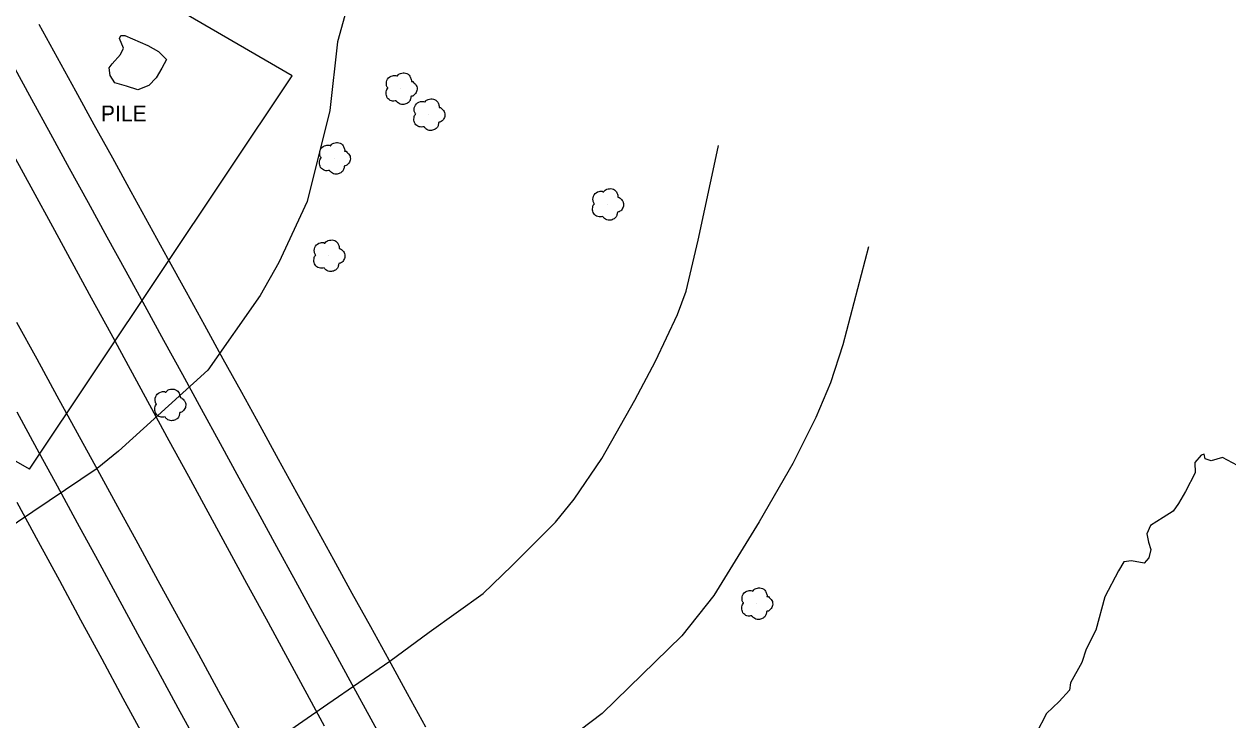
# Model space of a CAD drawing. Extents: x 368532 to 392481, y 10654822 to 10676899.
# Drawn here: x 374573.7 to 374954.4, y 10671554.3 to 10671774.3 of the extents above; entities that cross this region are included whole.
import ezdxf

# ---------------------------------------------------------------- set-up
doc = ezdxf.new("R2010")
doc.units = 0
for name, color, linetype in [('p_Catenary', 7, 'Continuous'), ('p_drainage conc drain', 7, 'Continuous'), ('p_dtm stock pile', 7, 'Continuous'), ('p_structure fence', 7, 'Continuous'), ('p_veg tree', 7, 'Continuous')]:
    doc.layers.add(name, color=color, linetype=linetype)

msp = doc.modelspace()

# ---------------------------------------------------------------- linework, layer by layer
at = {"layer": 'p_Catenary'}
for points in [[(374578.3, 10671774.37), (374584.13, 10671763.79), (374589.96, 10671753.21), (374595.79, 10671742.63), (374601.61, 10671732.04), (374607.44, 10671721.46), (374613.27, 10671710.88), (374619.09, 10671700.3), (374624.92, 10671689.71), (374630.75, 10671679.13), (374636.57, 10671668.55), (374642.4, 10671657.96), (374648.23, 10671647.38), (374654.05, 10671636.8), (374659.88, 10671626.22), (374665.71, 10671615.63), (374671.53, 10671605.05), (374677.36, 10671594.47), (374683.19, 10671583.89), (374689.01, 10671573.3), (374694.84, 10671562.72), (374700.67, 10671552.14)], [(374570.1, 10671761.46), (374576.06, 10671750.58), (374582.02, 10671739.7), (374587.98, 10671728.82), (374593.94, 10671717.94), (374599.9, 10671707.06), (374605.86, 10671696.18), (374611.82, 10671685.3), (374617.78, 10671674.41), (374623.74, 10671663.53), (374629.7, 10671652.65), (374635.66, 10671641.77), (374641.62, 10671630.89), (374647.58, 10671620.01), (374653.54, 10671609.13), (374659.5, 10671598.24), (374665.46, 10671587.36), (374671.42, 10671576.48), (374677.38, 10671565.6), (374683.34, 10671554.72), (374689.3, 10671543.84)], [(374570.35, 10671732.95), (374576.49, 10671721.68), (374582.64, 10671710.4), (374588.78, 10671699.12), (374594.92, 10671687.84), (374601.07, 10671676.56), (374607.21, 10671665.28), (374613.35, 10671654), (374619.49, 10671642.72), (374625.64, 10671631.44), (374631.78, 10671620.16), (374637.92, 10671608.88), (374644.07, 10671597.6), (374650.21, 10671586.32), (374656.35, 10671575.04), (374662.5, 10671563.77), (374668.64, 10671552.49)], [(374571.27, 10671680.15), (374577.66, 10671668.48), (374584.06, 10671656.8), (374590.45, 10671645.13), (374596.85, 10671633.46), (374603.24, 10671621.78), (374609.64, 10671610.11), (374616.03, 10671598.44), (374622.43, 10671586.76), (374628.82, 10671575.09), (374635.22, 10671563.41), (374641.61, 10671551.74)], [(374571.37, 10671651.76), (374577.74, 10671640.06), (374584.11, 10671628.37), (374590.49, 10671616.67), (374596.86, 10671604.97), (374603.23, 10671593.27), (374609.6, 10671581.57), (374615.98, 10671569.87), (374622.35, 10671558.18), (374628.72, 10671546.48)], [(374571.42, 10671623.19), (374578.13, 10671610.8), (374584.83, 10671598.41), (374591.54, 10671586.03), (374598.25, 10671573.64), (374604.96, 10671561.25), (374611.67, 10671548.87), (374618.38, 10671536.48), (374625.09, 10671524.09), (374631.79, 10671511.7), (374638.5, 10671499.32), (374645.21, 10671486.93), (374651.92, 10671474.54), (374658.63, 10671462.15), (374665.34, 10671449.77), (374672.05, 10671437.38), (374678.76, 10671424.99), (374685.46, 10671412.61), (374692.17, 10671400.22), (374698.88, 10671387.83), (374705.59, 10671375.44), (374712.3, 10671363.06), (374719.01, 10671350.67), (374726.57, 10671336.71)]]:
    msp.add_lwpolyline(points, dxfattribs=at)
at = {"layer": 'p_drainage conc drain'}
for p, q in [((374792.87, 10671733.96), (374793.34, 10671735.96)), ((374786.86, 10671706.02), (374792.87, 10671733.96)), ((374783.06, 10671689.89), (374786.86, 10671706.02)), ((374840.76, 10671703.9), (374832.62, 10671672.94)), ((374780.31, 10671682.56), (374783.06, 10671689.89)), ((374773.33, 10671667.73), (374780.31, 10671682.56)), ((374832.62, 10671672.94), (374828.68, 10671660.91)), ((374766.89, 10671655.44), (374773.33, 10671667.73)), ((374828.68, 10671660.91), (374824.06, 10671649.94)), ((374756.45, 10671637.03), (374766.89, 10671655.44)), ((374824.06, 10671649.94), (374816.86, 10671635.44)), ((374747.63, 10671624.16), (374756.45, 10671637.03)), ((374816.86, 10671635.44), (374806.21, 10671616.93)), ((374741.78, 10671616.88), (374747.63, 10671624.16)), ((374727.96, 10671603.11), (374741.78, 10671616.88)), ((374806.21, 10671616.93), (374791.79, 10671593.69)), ((374718.88, 10671594.34), (374727.96, 10671603.11)), ((374701.83, 10671582.11), (374718.88, 10671594.34)), ((374791.79, 10671593.69), (374781.69, 10671580.9)), ((374689.39, 10671572.92), (374701.83, 10671582.11)), ((374781.69, 10671580.9), (374756.56, 10671556.42)), ((374669.77, 10671559.47), (374689.39, 10671572.92)), ((374634.73, 10671535.28), (374669.77, 10671559.47)), ((374756.56, 10671556.42), (374740.12, 10671544.02))]:
    msp.add_line(p, q, dxfattribs=at)
at = {"layer": 'p_dtm stock pile'}
for p, q in [((374603.87, 10671769.84), (374604.33, 10671770.7)), ((374605.07, 10671766.74), (374603.87, 10671769.84)), ((374604.33, 10671770.7), (374605.59, 10671770.74)), ((374605.59, 10671770.74), (374612.83, 10671767.61)), ((374604.14, 10671764.74), (374605.07, 10671766.74)), ((374612.83, 10671767.61), (374616.18, 10671765.7)), ((374616.18, 10671765.7), (374618.75, 10671763.13)), ((374600.57, 10671760.49), (374601.58, 10671761.82)), ((374601.58, 10671761.82), (374604.14, 10671764.74)), ((374618.75, 10671763.13), (374617.24, 10671760.45)), ((374600.95, 10671758.14), (374600.57, 10671760.49)), ((374602.39, 10671755.81), (374600.95, 10671758.14)), ((374617.24, 10671760.45), (374615.41, 10671757.37)), ((374606.02, 10671754.75), (374602.39, 10671755.81)), ((374609.68, 10671753.61), (374606.02, 10671754.75)), ((374613.17, 10671754.97), (374609.68, 10671753.61)), ((374615.41, 10671757.37), (374613.17, 10671754.97)), ((374945.92, 10671638.02), (374943.94, 10671635.74)), ((374946.91, 10671638.33), (374945.92, 10671638.02)), ((374947.25, 10671636.93), (374946.91, 10671638.33)), ((374949.09, 10671636.23), (374947.25, 10671636.93)), ((374952.73, 10671637.29), (374949.09, 10671636.23)), ((374960.66, 10671633.09), (374952.73, 10671637.29)), ((374944.12, 10671632.42), (374941.03, 10671626.54)), ((374943.94, 10671635.74), (374944.12, 10671632.42)), ((374941.03, 10671626.54), (374938.8, 10671622.74)), ((374938.8, 10671622.74), (374937.15, 10671620.39)), ((374933.91, 10671618.31), (374929.94, 10671615.86)), ((374937.15, 10671620.39), (374933.91, 10671618.31)), ((374929.94, 10671615.86), (374928.76, 10671613.21)), ((374928.76, 10671613.21), (374929.31, 10671610.51)), ((374929.31, 10671610.51), (374930.01, 10671608.24)), ((374929.46, 10671605.61), (374927.97, 10671603.95)), ((374930.01, 10671608.24), (374929.46, 10671605.61)), ((374921.48, 10671604.35), (374919.78, 10671601.49)), ((374923.96, 10671604.59), (374921.48, 10671604.35)), ((374927.97, 10671603.95), (374923.96, 10671604.59)), ((374919.78, 10671601.49), (374915.54, 10671593.27)), ((374915.54, 10671593.27), (374912.61, 10671582.69)), ((374912.61, 10671582.69), (374909.61, 10671576.67)), ((374909.61, 10671576.67), (374908.19, 10671572.52)), ((374908.19, 10671572.52), (374904.69, 10671566.05)), ((374904.29, 10671563.72), (374901.06, 10671560.19)), ((374904.69, 10671566.05), (374904.29, 10671563.72)), ((374901.06, 10671560.19), (374897.02, 10671556.35)), ((374897.02, 10671556.35), (374893.8, 10671550.08))]:
    msp.add_line(p, q, dxfattribs=at)
at = {"layer": 'p_structure fence'}
for p, q in [((374658.48, 10671758.02), (374547.92, 10671822.11)), ((374678.84, 10671790.63), (374672.85, 10671768.78)), ((374672.85, 10671768.78), (374670.36, 10671747.04)), ((374575.39, 10671633.62), (374658.48, 10671758.02)), ((374670.36, 10671747.04), (374663.22, 10671718.26)), ((374663.22, 10671718.26), (374654.3, 10671698.96)), ((374575.39, 10671633.62), (374456.31, 10671701.4)), ((374654.3, 10671698.96), (374648.38, 10671688.49)), ((374648.38, 10671688.49), (374631.82, 10671664.89)), ((374631.82, 10671664.89), (374603.58, 10671639.35)), ((374603.58, 10671639.35), (374596.79, 10671633.83)), ((374596.79, 10671633.83), (374566.47, 10671613.44))]:
    msp.add_line(p, q, dxfattribs=at)
at = {"layer": 'p_veg tree'}
for p, q in [((374692.86, 10671753.98), (374692.86, 10671753.98)), ((374701.64, 10671745.77), (374701.64, 10671745.77)), ((374671.77, 10671731.95), (374671.77, 10671731.95)), ((374758.16, 10671717.38), (374758.16, 10671717.38)), ((374670.02, 10671701.16), (374670.02, 10671701.16)), ((374619.71, 10671654.02), (374619.71, 10671654.02)), ((374805.34, 10671591.15), (374805.34, 10671591.15))]:
    msp.add_line(p, q, dxfattribs=at)
for points in [[(374691.4, 10671750.08), (374689.84, 10671750.09), (374688.56, 10671751.07), (374688.18, 10671752.52), (374688.3, 10671753.37), (374688.64, 10671753.98), (374688.75, 10671754.09), (374688.69, 10671754.18), (374688.31, 10671755.06), (374688.66, 10671756.96), (374690.25, 10671758.03), (374691.55, 10671757.95), (374691.69, 10671757.9), (374691.76, 10671758), (374692.73, 10671758.73), (374694.34, 10671758.85), (374695.7, 10671757.88), (374696.12, 10671756.87), (374696.18, 10671756.32), (374696.16, 10671756.21), (374696.27, 10671756.22), (374696.87, 10671755.91), (374697.71, 10671754.94), (374697.93, 10671753.39), (374697.29, 10671752.15), (374696.34, 10671751.53), (374696.08, 10671751.47), (374696.03, 10671751.42), (374696.02, 10671751.36), (374695.96, 10671750.91), (374695.63, 10671749.99), (374694.69, 10671749.22), (374693.47, 10671748.9), (374691.96, 10671749.46), (374691.38, 10671750.09)], [(374700.18, 10671741.87), (374698.62, 10671741.88), (374697.34, 10671742.86), (374696.97, 10671744.32), (374697.08, 10671745.16), (374697.43, 10671745.77), (374697.53, 10671745.88), (374697.47, 10671745.98), (374697.1, 10671746.86), (374697.44, 10671748.76), (374699.03, 10671749.83), (374700.33, 10671749.74), (374700.47, 10671749.7), (374700.54, 10671749.79), (374701.52, 10671750.52), (374703.13, 10671750.65), (374704.49, 10671749.67), (374704.9, 10671748.67), (374704.96, 10671748.12), (374704.95, 10671748.01), (374705.05, 10671748.01), (374705.65, 10671747.71), (374706.49, 10671746.74), (374706.71, 10671745.18), (374706.07, 10671743.94), (374705.12, 10671743.33), (374704.86, 10671743.26), (374704.81, 10671743.22), (374704.8, 10671743.15), (374704.74, 10671742.7), (374704.41, 10671741.79), (374703.47, 10671741.02), (374702.25, 10671740.7), (374700.75, 10671741.25), (374700.16, 10671741.88)], [(374670.31, 10671728.06), (374668.75, 10671728.07), (374667.47, 10671729.05), (374667.09, 10671730.5), (374667.21, 10671731.35), (374667.55, 10671731.96), (374667.65, 10671732.07), (374667.59, 10671732.16), (374667.22, 10671733.04), (374667.57, 10671734.94), (374669.15, 10671736.01), (374670.45, 10671735.93), (374670.59, 10671735.88), (374670.67, 10671735.98), (374671.64, 10671736.71), (374673.25, 10671736.83), (374674.61, 10671735.86), (374675.03, 10671734.85), (374675.09, 10671734.3), (374675.07, 10671734.19), (374675.18, 10671734.19), (374675.78, 10671733.89), (374676.61, 10671732.92), (374676.84, 10671731.36), (374676.2, 10671730.13), (374675.24, 10671729.51), (374674.99, 10671729.45), (374674.94, 10671729.4), (374674.93, 10671729.34), (374674.87, 10671728.88), (374674.53, 10671727.97), (374673.59, 10671727.2), (374672.37, 10671726.88), (374670.87, 10671727.44), (374670.28, 10671728.06)], [(374756.7, 10671713.48), (374755.15, 10671713.49), (374753.86, 10671714.47), (374753.49, 10671715.93), (374753.6, 10671716.77), (374753.95, 10671717.38), (374754.05, 10671717.49), (374753.99, 10671717.59), (374753.62, 10671718.47), (374753.96, 10671720.37), (374755.55, 10671721.44), (374756.85, 10671721.35), (374756.99, 10671721.31), (374757.06, 10671721.4), (374758.04, 10671722.13), (374759.65, 10671722.26), (374761.01, 10671721.28), (374761.43, 10671720.28), (374761.48, 10671719.73), (374761.47, 10671719.62), (374761.57, 10671719.62), (374762.17, 10671719.32), (374763.01, 10671718.35), (374763.23, 10671716.79), (374762.59, 10671715.55), (374761.64, 10671714.94), (374761.38, 10671714.87), (374761.33, 10671714.83), (374761.32, 10671714.76), (374761.26, 10671714.31), (374760.93, 10671713.4), (374759.99, 10671712.63), (374758.77, 10671712.31), (374757.27, 10671712.86), (374756.68, 10671713.49)], [(374668.56, 10671697.26), (374667, 10671697.27), (374665.72, 10671698.25), (374665.35, 10671699.71), (374665.46, 10671700.55), (374665.81, 10671701.16), (374665.91, 10671701.27), (374665.85, 10671701.36), (374665.48, 10671702.25), (374665.82, 10671704.15), (374667.41, 10671705.22), (374668.71, 10671705.13), (374668.85, 10671705.08), (374668.92, 10671705.18), (374669.9, 10671705.91), (374671.51, 10671706.03), (374672.87, 10671705.06), (374673.28, 10671704.05), (374673.34, 10671703.51), (374673.33, 10671703.4), (374673.43, 10671703.4), (374674.03, 10671703.1), (374674.87, 10671702.13), (374675.09, 10671700.57), (374674.45, 10671699.33), (374673.5, 10671698.71), (374673.24, 10671698.65), (374673.19, 10671698.6), (374673.18, 10671698.54), (374673.12, 10671698.09), (374672.79, 10671697.17), (374671.85, 10671696.41), (374670.63, 10671696.09), (374669.13, 10671696.64), (374668.54, 10671697.27)], [(374618.25, 10671650.12), (374616.69, 10671650.13), (374615.41, 10671651.11), (374615.03, 10671652.56), (374615.15, 10671653.41), (374615.49, 10671654.02), (374615.6, 10671654.13), (374615.54, 10671654.22), (374615.16, 10671655.11), (374615.51, 10671657), (374617.1, 10671658.07), (374618.4, 10671657.99), (374618.54, 10671657.94), (374618.61, 10671658.04), (374619.58, 10671658.77), (374621.19, 10671658.89), (374622.55, 10671657.92), (374622.97, 10671656.91), (374623.03, 10671656.37), (374623.01, 10671656.25), (374623.12, 10671656.26), (374623.72, 10671655.95), (374624.55, 10671654.98), (374624.78, 10671653.43), (374624.14, 10671652.19), (374623.19, 10671651.57), (374622.93, 10671651.51), (374622.88, 10671651.46), (374622.87, 10671651.4), (374622.81, 10671650.95), (374622.48, 10671650.03), (374621.54, 10671649.26), (374620.32, 10671648.94), (374618.81, 10671649.5), (374618.23, 10671650.13)], [(374803.88, 10671587.25), (374802.32, 10671587.26), (374801.04, 10671588.24), (374800.66, 10671589.69), (374800.78, 10671590.54), (374801.12, 10671591.15), (374801.23, 10671591.26), (374801.17, 10671591.35), (374800.79, 10671592.23), (374801.14, 10671594.13), (374802.73, 10671595.2), (374804.02, 10671595.12), (374804.16, 10671595.07), (374804.24, 10671595.17), (374805.21, 10671595.9), (374806.82, 10671596.02), (374808.18, 10671595.05), (374808.6, 10671594.04), (374808.66, 10671593.5), (374808.64, 10671593.38), (374808.75, 10671593.39), (374809.35, 10671593.08), (374810.18, 10671592.11), (374810.41, 10671590.56), (374809.77, 10671589.32), (374808.82, 10671588.7), (374808.56, 10671588.64), (374808.51, 10671588.59), (374808.5, 10671588.53), (374808.44, 10671588.08), (374808.1, 10671587.16), (374807.17, 10671586.39), (374805.95, 10671586.07), (374804.44, 10671586.63), (374803.86, 10671587.26)]]:
    msp.add_spline(points, degree=3, dxfattribs=at)

# ---------------------------------------------------------------- texts
at = {"layer": 'p_dtm stock pile'}
msp.add_text(' PILE', height=5, dxfattribs=at).set_placement((374596.1, 10671743.6))

doc.saveas('drawing.dxf')
